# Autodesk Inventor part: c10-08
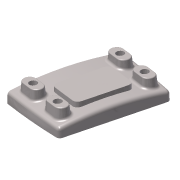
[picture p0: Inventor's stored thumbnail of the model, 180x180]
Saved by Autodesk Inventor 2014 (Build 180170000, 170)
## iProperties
Created: 2010-12
Part Number: c10-08
Material: Generic
Document SubType Name: Modeling
Designer: Thom Tremblay
Density: 1 g/cm^3
Appearance: Generic
Author: Thom Tremblay
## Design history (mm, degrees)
sketch "Sketch1"
  geometry: L1 (-60, -12)-(60, -12); L2 (60, -12)-(60, 12); L3 (60, 12)-(-60, 12); L4 (-60, 12)-(-60, -12); A1 r 350 centre (0, -332.819) between (60, 12) and (-60, 12); A2 r 350 centre (0, 332.819) between (-60, -12) and (60, -12); 3 further points
  constraints: 8 end point, 4 point on circle, 2 centre point, 2 midpoint, 2 parallel, 1 equal radius, 1 horizontal, 1 horizontal alignment, 1 perpendicular, 1 vertical alignment
  dimensions: "d0" = 120 distance of L3.end L2.end; "d1" = 24 distance of L2.end L1.end; "d2" = 350 radius of A1
workplane "Work Plane4"
sketch "Sketch5"
  geometry: L1 (-60, 12)-(-60, -12) reference; L2 (60, -12)-(60, 12) reference; L3 (-58, 10.314)-(-58, -10.314); L4 (58, -10.314)-(58, 10.314); A1 r 350 centre (0, 332.819) between (-60, -12) and (60, -12) reference; A2 r 350 centre (0, -332.819) between (60, 12) and (-60, 12) reference; A3 r 348 centre (0, 332.819) between (-58, -10.314) and (58, -10.314); A4 r 348 centre (0, -332.819) between (58, 10.314) and (-58, 10.314); 1 further point
  constraints: 4 end point, 4 point on circle, 2 centre point, 3 other
  dimensions: "d37" = 2 distance between parallel lines of L2 L4
sketch "Sketch6"
  geometry: L1 (-60, 0)-(60, 0); L2 (60, 0)-(58.843, 22.085); L3 (-60, 0)-(-58.779, 23.307); A1 r 691.758 centre (630.81, -36.204) between (-60, 0) and (-58, -100); A2 r 691.758 centre (-630.81, -36.204) between (58, -100) and (60, 0); 1 further point
  constraints: 6 end point, 4 point on circle, 2 centre point, 2 tangent, 1 horizontal
  dimensions: "d53" = 87 deg angle of L1 L3; "d54" = 87 deg angle of L1 L2 (= d53)
sketch "Sketch7"
  geometry: L1 (17.181, 0)-(12, 0) reference; L2 (15.181, -100)-(10.314, -100) reference; L3 (17.181, 0)-(16.768, 11.838); A1 r 911.322 centre (-893.585, -31.805) between (15.181, -100) and (17.181, 0); 1 further point
  constraints: 2 end point, 2 point on circle, 1 centre point, 1 tangent
  dimensions: "d56" = 88 deg angle of L1 L3
feature "LoftSrf2" sketch "Sketch5", "Sketch6", "Sketch7" dims "d57" = 0, "d58" = 90 deg, "d59" = 0, "d60" = 90 deg, "d61" = 0, "d62" = 90 deg, "d63" = 0, "d64" = 90 deg, "d65" = 0, "d66" = 90 deg
sketch "Sketch2"
  geometry: L1 (-75, -16)-(75, -16); L2 (-75, -60)-(75, -60); A1 r 183.781 centre (0, -183.781) between (75, -16) and (-75, -16); 2 further points
  constraints: 4 end point, 3 point on circle, 1 centre point, 1 coincident, 1 horizontal, 1 parallel
  dimensions: "d5" = 16 distance from line of point (0, 0) L1; "d7" = 60 distance from line of point (0, 0) L2; "d55" = 150 distance of L1.start L1.end
feature "RevolutionSrf1" sketch "Sketch2" dims angle "d8" = 40 deg
patch "Boundary Patch1" dims "d13" = 0, "d67" = 0, "d68" = 0, "d69" = 0, "d70" = 0
workplane "Work Plane1"
sketch "Sketch3"
  geometry: L1 (52, -85)-(52, -73); L2 (38, -73)-(38, -85); A1 r 7 centre (45, -73) between (52, -73) and (38, -73); A2 r 7 centre (45, -85) between (38, -85) and (52, -85); 1 further point
  constraints: 4 end point, 4 point on circle, 4 tangent, 2 centre point, 1 parallel, 1 vertical
  dimensions: "d15" = 12 distance of L1.start L1.end; "d16" = 7 radius of A1; "d50" = 45 horizontal distance of A1.centre point (0, 0); "d51" = 85 vertical distance of point (0, 0) A2.centre
extrude_surface "ExtrusionSrf2" sketch "Sketch3" dims "d19" = 14, "d20" = 5 deg
pattern_linear "Rectangular Pattern1" dims "d23" = 90
workplane "Work Plane2"
feature "Sculpt1"
sketch "Sketch4"
  geometry: L1 (-24.5, 6)-(24.5, 6); L2 (27.5, 3)-(27.5, -3); L3 (24.5, -6)-(-24.5, -6); L4 (-27.5, -3)-(-27.5, 3); A1 r 3 centre (-24.5, 3) between (-24.5, 6) and (-27.5, 3); A2 r 3 centre (24.5, 3) between (27.5, 3) and (24.5, 6); A3 r 3 centre (24.5, -3) between (24.5, -6) and (27.5, -3); A4 r 3 centre (-24.5, -3) between (-27.5, -3) and (-24.5, -6); 6 further points
  constraints: 8 end point, 8 point on circle, 8 tangent, 6 point on line, 4 centre point, 3 equal radius, 2 midpoint, 2 parallel, 1 horizontal, 1 horizontal alignment, 1 perpendicular, 1 vertical alignment
  dimensions: "d28" = 55 distance of point (27.5, -6) point (-27.5, -6); "d29" = 12 distance of point (27.5, 6) point (27.5, -6); "d30" = 3 radius of A1
extrude_surface "ExtrusionSrf6" sketch "Sketch4" dims "d31" = 14, "d32" = 45 deg
patch "Boundary Patch2" dims "d33" = 0, "d34" = 0
fillet "Fillet1" dims "d79" = 4, "d80" = 3, "d81" = 1
feature "Sculpt2"
node "Splitting Plane 1"
shell "Shell1" dims "d83" = 2
split "Split1"
  body "Solid1"
feature "Lip1" dims "d149" = 1, "d150" = 1, "d151" = 0, "d152" = 0, "d153" = 0, "d154" = 0
feature "Lip2" dims "d155" = 1, "d156" = 1, "d157" = 0, "d158" = 0, "d159" = 0, "d160" = 0.5
split "Split3"
  node "Back"
sketch "Sketch9"
  geometry: L1 (50.167, -73)-(50.167, -85) reference; L2 (39.833, -85)-(39.833, -73) reference; L3 (45, -73)-(45, -85); L4 (45, -85)-(39.833, -85); A1 r 5.167 centre (45, -73) between (50.167, -73) and (39.833, -73) reference; A2 r 5.167 centre (45, -85) between (39.833, -85) and (50.167, -85) reference; 5 further points
  constraints: 4 end point, 1 horizontal, 1 midpoint, 1 parallel, 1 perpendicular, 1 vertical, 3 other
  dimensions: "d86" = 90 distance of point (45, -79) point (-45, -79); "d89" = 40 distance of point (45, -79) point (45, -39)
  node "Projected Loop1"
feature "Boss1" dims "d92" = 0, "d93" = 0, "d94" = 7, "d95" = 2, "d96" = 0.5, "d97" = 6, "d98" = 1.25, "d99" = 3.5, "d100" = 2.5 deg, "d101" = 2.5 deg, "d102" = 2.5 deg, "d103" = 2.5 deg, "d104" = 90 deg, "d107" = 2, "d108" = 2, "d109" = 10, "d110" = 0, "d111" = 10 deg, "d112" = 2.5 deg, "d113" = 0, "d114" = 0, "d115" = 0, "d116" = 360 deg
feature "Boss2" dims "d117" = 3, "d118" = 0, "d119" = 6, "d120" = 3, "d121" = 9.5, "d122" = 2 deg, "d123" = 1 deg, "d126" = 2, "d127" = 2, "d128" = 10, "d129" = 0, "d130" = 10 deg, "d131" = 2.5 deg, "d132" = 0, "d133" = 0, "d134" = 0, "d135" = 360 deg
workplane "Work Plane6"
sketch "Sketch10"
  geometry: L1 (24, -85)-(-24, -85); L2 (-30, -79)-(-30, -51); L3 (-24, -45)-(24, -45); L4 (30, -51)-(30, -79); L5 (54.344, -100)-(-54.344, -100) reference; A1 r 6 centre (-24, -51) between (-24, -45) and (-30, -51); A2 r 6 centre (24, -51) between (30, -51) and (24, -45); A3 r 6 centre (24, -79) between (24, -85) and (30, -79); A4 r 6 centre (-24, -79) between (-30, -79) and (-24, -85); 5 further points
  constraints: 8 end point, 8 point on circle, 8 tangent, 6 point on line, 4 centre point, 3 equal radius, 2 parallel, 1 horizontal, 1 midpoint, 1 perpendicular, 1 vertical alignment
  dimensions: "d137" = 60 distance of point (-30, -45) point (30, -45); "d138" = 40 distance of point (-30, -85) point (-30, -45); "d139" = 15 distance between parallel lines of L5 L1; "d141" = 6 radius of A2
feature "Rest1" sketch "Sketch10" dims "d142" = 5, "d143" = 0, "d144" = 0, "d145" = 0, "d146" = 2 deg, "d147" = 2 deg, "d148" = 2
body "Srf2"
body "Srf3"
body "Srf4"
body "Srf5"
body "Srf6"
body "Srf7"
body "Srf8"
body "Srf9"
body "Srf11"
feature "Stitch Surface1"
body "Srf12"
extrude_surface "ExtrusionSrf3"
extrude_surface "ExtrusionSrf4"
extrude_surface "ExtrusionSrf5"
node "Front"
node "Back - Top"
node "Back - Bottom"
other parameters: "d14" = -24, "d52" = -6
